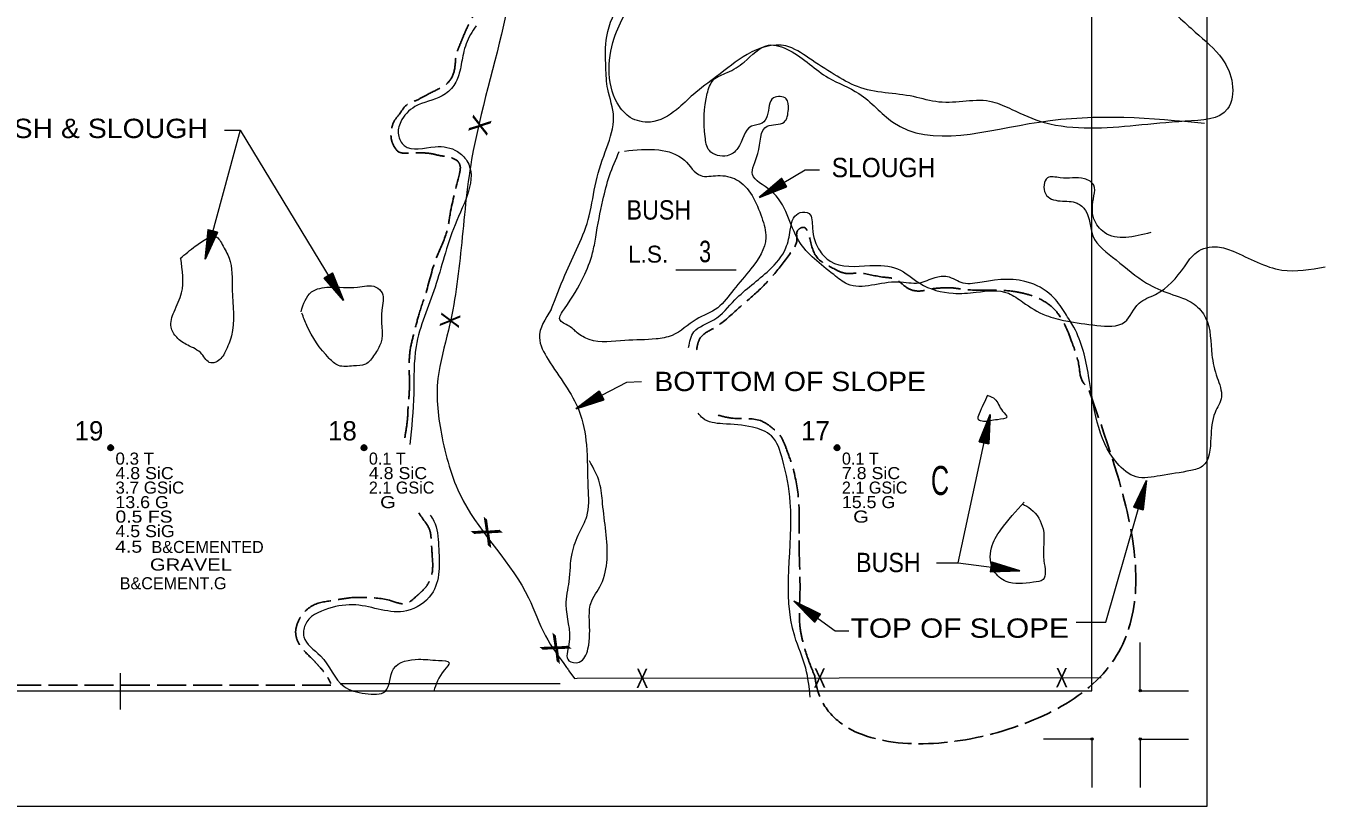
# Model space of a CAD drawing. Extents: x -577 to 499, y -450 to 700.
# Drawn here: x -39 to 499, y -450 to -127 of the extents above; entities that cross this region are included whole.
import ezdxf
from ezdxf.enums import TextEntityAlignment as Align

# ---------------------------------------------------------------- set-up
doc = ezdxf.new("R2010")
doc.units = 0
doc.header["$LTSCALE"] = 2
doc.header["$PDMODE"] = 32
doc.header["$PDSIZE"] = 1
doc.linetypes.add('LONG_DASHED', pattern=[7.5, 6, -1.5])
for name, color, linetype, lineweight in [('1', 7, 'Continuous', 13), ('2', 7, 'Continuous', 35), ('3', 7, 'Continuous', 13), ('4', 7, 'Continuous', 25)]:
    doc.layers.add(name, color=color, linetype=linetype, lineweight=lineweight)

msp = doc.modelspace()

# ---------------------------------------------------------------- linework, layer by layer
at = {"layer": '1'}
for p, q in [((230.048, -228.15), (255.048, -228.15)), ((422.281, -402.333), (422.281, -382.333)), ((-0.017, -395.027), (-0.017, -410.027)), ((-402.391, -402.333), (402.281, -402.333)), ((422.281, -402.333), (442.281, -402.333)), ((402.281, -422.333), (382.281, -422.333)), ((402.281, -422.333), (402.281, -442.333)), ((422.281, -422.333), (422.281, -442.333)), ((422.281, -422.333), (442.281, -422.333)), ((-450.017, -450.027), (449.983, -450.027))]:
    msp.add_line(p, q, dxfattribs=at)
for points in [[(449.983, -450.027), (449.983, 399.973), (449.983, 699.973), (-450.017, 699.973), (-450.017, 49.973), (-450.017, -450.027)], [(402.281, -402.333), (402.281, 402.339), (-402.391, 402.339)]]:
    msp.add_lwpolyline(points, dxfattribs=at)
for p in [(422.281, -402.333), (402.281, -422.333), (422.281, -422.333)]:
    msp.add_point(p, dxfattribs=at)
at = {"layer": '2', "linetype": 'LONG_DASHED', "lineweight": 25}
msp.add_line((87.286, -400), (-302.391, -400), dxfattribs=at)
at = {"layer": '2'}
for centre in [(-3.938, -301.775), (100.962, -301.775), (296.775, -301.775)]:
    msp.add_circle(centre, 1, dxfattribs=at)
at = {"layer": '2', "linetype": 'LONG_DASHED', "lineweight": 25}
for points in [[(131.994, -74.666), (132.56, -78.069), (134.001, -82.389), (135.983, -85.629), (138.686, -87.969), (145.714, -96.068), (149.859, -100.748), (151.48, -107.767), (149.138, -116.767), (143.912, -127.386), (142.29, -130.986), (140.669, -134.946), (139.227, -138.906), (138.326, -145.745), (135.443, -150.965), (133.1, -152.585), (126.793, -155.825), (122.288, -158.165), (118.144, -160.324), (115.621, -163.744), (113.639, -166.264), (112.377, -169.864), (112.197, -173.644), (113.098, -176.524), (115.441, -179.403), (118.864, -179.943), (123.91, -179.763), (128.956, -180.123), (133.1, -181.023), (136.524, -181.563), (139.587, -183.003)], [(139.587, -183.003), (140.609, -184.619), (140.45, -188.43), (136.635, -204.944), (135.204, -212.406), (131.071, -222.727), (126.62, -237.494), (123.758, -246.386), (121.851, -253.531), (120.261, -260.2), (119.625, -267.345), (119.784, -274.649), (119.466, -282.112), (119.148, -285.764)], [(238.624, -261.328), (238.966, -259.398), (240.252, -256.186), (245.72, -252.331), (255.69, -244.3), (263.087, -237.875), (270.484, -230.165), (277.559, -221.17), (280.132, -215.709), (280.454, -211.854), (282.705, -210.569), (285.6, -215.709), (288.816, -223.419), (295.891, -227.916), (299.751, -229.523), (305.54, -229.523), (315.51, -231.129), (320.977, -232.093), (325.801, -235.626), (329.661, -236.911), (336.736, -235.947), (340.596, -235.626), (344.133, -235.626), (349.601, -236.269), (362.787, -236.59), (370.827, -237.232), (376.295, -238.517), (383.37, -241.73), (388.195, -246.227), (393.984, -258.113), (396.878, -267.75), (398.486, -274.496), (401.059, -278.03), (401.165, -278.247)], [(401.059, -278.03), (401.168, -400.823), (288.505, -401.296), (287.529, -396.247)], [(119.148, -285.764), (118.691, -292.346), (117.797, -298.15), (117.771, -298.415)], [(287.529, -396.247), (285.6, -391.428), (282.384, -381.149), (281.419, -375.687), (281.419, -361.553), (281.097, -344.206), (280.776, -322.683), (278.203, -309.19), (275.63, -301.802), (273.378, -296.983), (270.162, -293.771), (265.016, -290.558), (253.76, -289.595), (247.508, -288.277)], [(123.608, -328.731), (126.066, -332.302), (128.077, -335.651), (128.748, -339.669), (129.195, -346.588), (128.971, -354.401), (127.854, -357.303), (126.29, -359.758), (124.055, -361.99), (122.267, -363.553), (118.468, -366.232), (112.21, -365.116), (101.26, -363.776), (96.343, -363.776), (88.522, -364.892), (80.03, -366.901), (76.23, -369.803), (73.549, -374.044), (72.655, -378.285), (73.325, -381.411), (75.113, -384.536), (80.03, -389.67), (82.041, -391.902), (85.393, -395.92), (87.181, -399.268)]]:
    msp.add_spline(points, degree=3, dxfattribs=at)
at = {"layer": '2'}
for points in [[(-3.948, -300.888), (-3.218, -301.292), (-3.067, -302.14), (-3.752, -302.668), (-4.561, -302.438), (-4.847, -301.68), (-4.6, -301.118), (-4.027, -300.95), (-3.353, -301.444), (-3.37, -302.185), (-3.887, -302.444), (-4.409, -302.275), (-4.634, -301.629), (-4.05, -301.163), (-3.611, -301.697), (-3.651, -302.18), (-4.28, -302.045), (-4.134, -301.41), (-3.842, -301.961)], [(100.951, -300.888), (101.682, -301.292), (101.833, -302.14), (101.148, -302.668), (100.339, -302.438), (100.053, -301.68), (100.3, -301.118), (100.873, -300.95), (101.547, -301.444), (101.53, -302.185), (101.013, -302.444), (100.491, -302.275), (100.266, -301.629), (100.85, -301.163), (101.288, -301.697), (101.249, -302.18), (100.62, -302.045), (100.766, -301.41), (101.058, -301.961)], [(296.764, -300.888), (297.495, -301.292), (297.646, -302.14), (296.961, -302.668), (296.152, -302.438), (295.866, -301.68), (296.113, -301.118), (296.686, -300.95), (297.36, -301.444), (297.343, -302.185), (296.826, -302.444), (296.304, -302.275), (296.079, -301.629), (296.663, -301.163), (297.101, -301.697), (297.062, -302.18), (296.433, -302.045), (296.579, -301.41), (296.871, -301.961)]]:
    msp.add_spline(points, degree=3, dxfattribs=at)
at = {"layer": '3'}
for p, q in [((189.244, -397.172), (406.028, -396.88)), ((91.415, -399.313), (182.147, -399.313))]:
    msp.add_line(p, q, dxfattribs=at)
msp.add_lwpolyline([(185.769, -394.07), (188.121, -397.302), (189.244, -397.172)], dxfattribs=at)
for points in [[(248.573, 33.881), (218.878, -3.63), (196.171, -32.418), (168.223, -83.015), (159.489, -123.144), (145.515, -182.465), (141.148, -219.104), (135.908, -253.127), (131.541, -273.191), (133.288, -297.617), (142.021, -323.788), (169.096, -363.917), (176.083, -379.619), (184.817, -392.705), (185.769, -394.07)], [(234.45, -55.931), (268.542, -55.612), (301.36, -75.026), (333.859, -77.89), (353.932, -81.709), (374.005, -90.301), (393.44, -96.03), (404.91, -101.122), (419.885, -107.487), (431.356, -117.034), (445.056, -129.764), (456.208, -140.903), (460.35, -151.087), (458.438, -161.589), (440.914, -166.681), (401.406, -169.545), (382.607, -167.318), (369.225, -161.907), (361.26, -158.725), (338.957, -158.725), (328.442, -156.497), (305.183, -152.36), (295.625, -147.268), (285.11, -140.585), (275.552, -135.493), (259.621, -138.993), (246.876, -148.223), (237.318, -155.542), (230.308, -161.907), (219.475, -166.999), (211.191, -165.09), (206.731, -160.634), (204.5, -132.31), (214.377, -112.897), (220.431, -100.804), (224.892, -91.256), (228.078, -81.709), (230.308, -71.207), (232.857, -57.522)], [(178.419, -244.641), (184.088, -230.384), (194.184, -205.779), (197.01, -191.661), (201.453, -177.544), (204.279, -165.039), (201.856, -153.342), (201.049, -144.468), (201.453, -131.561), (207.51, -116.636), (217.202, -102.116), (225.278, -80.738), (227.297, -66.217), (230.932, -54.116)], [(147.328, -127.258), (145.017, -130.809), (142.082, -138.628), (140.614, -145.958), (138.168, -151.822), (133.276, -156.219), (122.023, -160.617), (116.153, -166.97), (115.174, -172.345), (117.62, -176.743), (130.34, -177.232), (139.635, -179.186), (143.549, -183.096), (138.657, -209.483), (130.34, -235.382), (122.513, -259.815), (121.534, -279.361), (119.972, -300.504)], [(426.64, -212.734), (407.45, -212.734), (403.089, -207.071), (403.089, -197.487), (403.089, -193.13), (399.164, -190.517), (389.132, -190.081), (383.899, -190.081), (383.026, -196.615), (389.132, -199.665), (396.111, -200.536), (399.6, -203.586), (402.653, -214.041), (412.248, -224.06), (424.896, -233.644), (434.491, -238), (444.522, -242.357), (449.319, -248.02), (451.936, -263.267), (454.117, -272.851), (455.861, -280.692), (453.244, -287.227), (451.5, -297.682), (448.011, -309.444), (443.213, -311.187), (430.565, -313.365), (420.534, -313.8), (412.684, -308.137), (400.908, -271.98), (394.802, -251.941), (391.313, -246.277), (386.516, -239.743), (376.921, -233.644), (356.858, -233.209), (349.008, -233.644), (342.466, -231.03), (337.232, -231.466), (330.69, -233.644), (321.967, -233.209), (301.033, -234.08), (295.363, -230.159), (280.971, -216.219), (269.195, -195.309), (261.781, -188.774), (263.961, -180.061), (267.886, -168.735), (274.865, -166.993), (276.609, -161.765), (275.737, -157.409), (270.503, -156.973), (267.886, -164.379), (265.706, -167.428), (261.344, -168.735), (255.675, -177.883), (251.313, -180.933), (243.899, -178.755), (242.154, -173.091), (243.027, -155.23), (245.643, -149.567), (251.313, -146.518), (258.291, -142.162), (268.323, -135.191), (277.045, -137.37), (293.182, -148.696), (305.83, -155.23), (319.787, -166.993), (380.41, -166.993), (448.883, -167.428)], [(208.743, -178.992), (222.957, -178.568), (233.564, -182.806), (240.353, -189.163), (247.354, -189.163), (255.203, -190.858), (265.598, -206.539), (267.295, -214.803), (261.143, -227.729), (253.93, -236.417), (247.354, -243.834), (238.444, -248.707), (228.473, -255.276), (221.896, -256.759), (208.955, -257.395), (194.105, -256.971), (189.226, -254.217), (185.831, -251.462), (182.013, -248.707), (183.922, -244.257), (191.771, -231.12), (195.59, -221.16), (196.863, -214.591), (199.833, -199.334), (202.591, -189.163), (206.622, -179.204)], [(235.32, -260.268), (237.523, -253.882), (245.772, -248.846), (254.48, -240.606), (268.687, -228.247), (275.562, -219.091), (277.395, -211.767), (278.77, -206.731), (281.52, -204.442), (285.186, -204.9), (286.561, -210.851), (289.769, -220.464), (293.894, -224.584), (310.393, -226.415), (321.85, -227.789), (331.017, -233.74), (344.766, -237.86), (354.39, -237.402), (367.681, -237.86), (373.639, -241.522), (383.263, -247.015), (391.512, -249.304), (404.345, -251.135), (415.802, -249.762), (421.76, -241.98), (428.635, -238.318), (440.551, -226.873), (445.592, -220.922), (454.3, -218.633), (460.716, -220.464), (480.881, -228.247), (498.755, -226.873)], [(24.892, -223.463), (31.094, -218.361), (36.202, -215.081), (39.121, -214.17), (42.222, -217.632), (45.141, -223.281), (46.418, -236.401), (46.054, -255.534), (43.499, -262.094), (40.216, -266.102), (37.479, -266.649), (33.831, -263.005), (27.993, -259.36), (23.432, -256.08), (21.061, -251.889), (22.338, -245.512), (25.439, -237.676), (25.074, -223.463)], [(74.877, -245.512), (79.256, -237.312), (86.553, -235.308), (98.228, -235.308), (105.89, -235.308), (108.445, -237.676), (108.262, -244.783), (107.897, -258.449), (105.343, -263.187), (101.512, -267.196), (96.587, -267.925), (90.384, -267.742), (86.553, -264.827), (77.249, -251.161), (75.242, -246.058)], [(178.419, -244.641), (173.552, -256.188), (177.203, -265.304), (189.98, -286.575), (193.022, -300.553), (193.63, -318.178), (193.022, -330.332), (189.98, -337.017), (186.938, -345.526), (185.721, -357.073), (184.504, -366.796), (185.721, -383.205), (185.721, -389.89), (189.98, -390.498), (193.63, -385.029), (194.239, -372.874), (194.847, -366.189), (199.106, -358.288), (201.54, -347.957), (199.715, -324.863), (198.498, -316.354), (194.239, -307.238)], [(359.23, -280.196), (362.081, -281.62), (365.287, -286.602), (367.069, -289.093), (363.149, -290.161), (357.449, -290.873), (355.311, -290.161), (355.667, -287.67), (357.449, -283.755), (359.23, -279.84)], [(285.645, -404.946), (283.811, -393.044), (279.228, -379.769), (277.395, -324.379), (274.187, -306.525), (269.604, -296.912), (261.813, -293.25), (249.439, -291.877), (241.189, -289.588), (239.245, -287.459)], [(373.482, -325.036), (377.045, -327.171), (382.033, -335.357), (382.389, -348.524), (382.033, -356.353), (378.113, -357.421), (366.712, -357.065), (361.724, -352.794), (360.655, -343.186), (364.575, -335.712), (374.194, -324.324)], [(128.352, -329.633), (129.851, -332.136), (131.808, -342.398), (128.873, -362.433), (118.599, -369.274), (97.562, -366.831), (86.31, -368.297), (76.526, -375.138), (76.036, -380.024), (82.886, -387.843), (92.67, -400.548), (101.476, -403.48), (109.793, -402.503), (113.217, -393.218), (123.491, -389.309), (131.808, -389.798), (136.211, -390.775), (134.254, -393.707), (129.851, -402.503)]]:
    msp.add_spline(points, degree=3, dxfattribs=at)
at = {"layer": '4', "lineweight": 13}
for p, q in [((49.679, -170.335), (35.181, -223.686)), ((346.907, -349.344), (372.432, -352.649))]:
    msp.add_line(p, q, dxfattribs=at)
for points in [[(43.193, -170.335), (49.679, -170.335), (92.409, -240.834)], [(289.545, -186.95), (283.557, -186.95), (264.472, -198.164)], [(215.794, -274.455), (209.616, -274.724), (188.664, -285.724)], [(337.927, -349.344), (346.907, -349.344), (360.142, -287.968)], [(395.813, -373.979), (408.019, -373.979), (424.874, -315.344)], [(301.637, -377.616), (296.046, -377.616), (278.872, -365.249)]]:
    msp.add_lwpolyline(points, dxfattribs=at)
at = {"layer": '4'}
for points in [[(264.472, -198.164), (275.832, -193.809), (273.806, -190.36)], [(35.181, -223.686), (40.258, -212.63), (36.398, -211.581)], [(92.409, -240.834), (87.9, -229.535), (84.479, -231.609)], [(188.664, -285.724), (200.218, -281.917), (198.359, -278.375)], [(360.142, -287.968), (355.658, -299.276), (359.568, -300.12)], [(424.874, -315.344), (419.637, -326.324), (423.481, -327.429)], [(372.432, -352.649), (360.788, -349.124), (360.274, -353.091)], [(278.872, -365.249), (287.441, -373.885), (289.778, -370.639)]]:
    msp.add_lwpolyline(points, close=True, dxfattribs=at)
for points in [[(275.687, -193.757), (264.968, -197.874), (273.748, -190.584), (275.561, -193.629), (265.603, -197.501), (273.667, -190.831), (275.338, -193.586), (266.274, -197.106), (273.61, -191.117), (275.117, -193.466), (267.047, -196.676), (273.503, -191.406), (274.818, -193.389), (267.973, -196.159), (273.466, -191.728), (274.501, -193.274), (268.97, -195.597), (273.389, -192.149), (274.158, -193.202), (270.086, -195.017), (273.223, -192.548), (273.747, -193.143), (271.361, -194.244), (273.073, -193.06)], [(40.118, -212.694), (35.332, -223.132), (36.514, -211.781), (39.939, -212.69), (35.525, -222.421), (36.628, -212.014), (39.749, -212.816), (35.729, -221.67), (36.787, -212.259), (39.507, -212.885), (35.982, -220.822), (36.912, -212.54), (39.239, -213.038), (36.282, -219.804), (37.112, -212.796), (38.933, -213.178), (36.602, -218.706), (37.351, -213.151), (38.637, -213.366), (36.994, -217.511), (37.511, -213.552), (38.301, -213.611), (37.365, -216.066), (37.762, -214.024)], [(87.849, -229.681), (92.112, -240.343), (84.704, -231.663), (87.723, -229.808), (91.731, -239.713), (84.951, -231.741), (87.683, -230.033), (91.327, -239.048), (85.238, -231.794), (87.566, -230.255), (90.887, -238.28), (85.528, -231.897), (87.493, -230.554), (90.357, -237.361), (85.851, -231.929), (87.383, -230.873), (89.781, -236.372), (86.273, -232), (87.315, -231.217), (89.186, -235.264), (86.674, -232.161), (87.262, -231.629), (88.395, -234), (87.189, -232.304)], [(200.076, -281.857), (189.172, -285.458), (198.291, -278.596), (199.957, -281.724), (189.824, -285.116), (198.198, -278.838), (199.735, -281.67), (190.513, -284.754), (198.127, -279.122), (199.52, -281.54), (191.306, -284.361), (198.006, -279.405), (199.226, -281.448), (192.257, -283.889), (197.955, -279.725), (198.915, -281.319), (193.279, -283.375), (197.858, -280.142), (198.575, -281.23), (194.421, -282.849), (197.673, -280.532), (198.168, -281.151), (195.732, -282.137), (197.498, -281.037)], [(355.794, -299.206), (360.02, -288.528), (359.442, -299.926), (355.973, -299.199), (359.865, -289.248), (359.315, -299.699), (356.156, -299.064), (359.701, -290.009), (359.143, -299.464), (356.394, -298.982), (359.494, -290.869), (359.003, -299.189), (356.653, -298.815), (359.248, -291.902), (358.791, -298.944), (356.952, -298.659), (358.986, -293.016), (358.533, -298.602), (357.238, -298.455), (358.658, -294.229), (358.352, -298.21), (357.56, -298.193), (358.364, -295.692), (358.076, -297.753)], [(419.778, -326.263), (424.715, -315.895), (423.368, -327.228), (419.957, -326.269), (424.511, -316.603), (423.257, -326.993), (420.149, -326.146), (424.296, -317.351), (423.102, -326.746), (420.392, -326.08), (424.032, -318.196), (422.981, -326.463), (420.661, -325.931), (423.716, -319.209), (422.785, -326.204), (420.97, -325.796), (423.38, -320.302), (422.551, -325.846), (421.269, -325.612), (422.971, -321.491), (422.397, -325.442), (421.607, -325.372), (422.579, -322.931), (422.153, -324.967)], [(360.87, -349.254), (371.863, -352.574), (360.457, -352.949), (360.891, -349.432), (371.132, -352.48), (360.672, -352.804), (361.042, -349.603), (370.36, -352.38), (360.892, -352.613), (361.143, -349.834), (369.486, -352.245), (361.154, -352.451), (361.331, -350.078), (368.437, -352.086), (361.381, -352.219), (361.511, -350.363), (367.305, -351.918), (361.7, -351.933), (361.738, -350.63), (366.068, -351.693), (362.075, -351.72), (362.026, -350.929), (364.586, -351.522), (362.508, -351.407)], [(287.431, -373.731), (279.337, -365.585), (289.55, -370.677), (287.497, -373.565), (279.935, -366.016), (289.292, -370.702), (287.446, -373.342), (280.566, -366.471), (289.007, -370.765), (287.466, -373.092), (281.272, -367.004), (288.7, -370.784), (287.417, -372.788), (282.119, -367.643), (288.39, -370.88), (287.393, -372.451), (283.035, -368.329), (287.974, -370.98), (287.321, -372.108), (284.017, -369.115), (287.542, -370.989), (287.209, -371.708), (285.239, -369.97), (287.013, -371.058)]]:
    msp.add_lwpolyline(points, dxfattribs=at)

# ---------------------------------------------------------------- texts
at = {"layer": '1'}
msp.add_text('L.S.', height=7, dxfattribs=at).set_placement((218.565, -225.168), align=Align.CENTER)
at = {"layer": '1', "width": 0.75}
msp.add_text('3', height=8.89, dxfattribs=at).set_placement((242.146, -225.012), align=Align.CENTER)
at = {"layer": '2'}
for s, p in [(' 19', (-6.938, -298.775)), (' 18', (97.962, -298.775)), (' 17', (293.775, -298.775))]:
    msp.add_text(s, height=8, dxfattribs=at).set_placement(p, align=Align.RIGHT)
for s, width, p in [('0.3 T      ', 1.05, (-1.938, -308.775)), ('4.8 SiC    ', 1.1, (-1.938, -314.775)), ('4.8 SiC    ', 1.1, (102.962, -314.775)), ('7.8 SiC    ', 1.1, (298.775, -314.775)), ('3.7 GSiC   ', 1.05, (-1.938, -320.775)), ('13.6 G     ', 1.1, (-1.938, -326.775)), ('  G        ', 1.25, (102.962, -326.775)), ('15.5 G     ', 1.1, (298.775, -326.775)), ('0.5 FS     ', 1.2, (-1.938, -332.775)), ('  G        ', 1.25, (298.775, -332.775)), ('4.5 SiG    ', 1.1, (-1.938, -338.775)), ('4.5        ', 1.2, (-2.047, -345.21)), ('GRAVEL     ', 1.25, (12.347, -352.606))]:
    msp.add_text(s, height=5, dxfattribs=dict(at, width=width)).set_placement(p)
for s, p in [('0.1 T      ', (102.962, -308.775)), ('0.1 T      ', (298.775, -308.775)), ('2.1 GSiC   ', (102.962, -320.775)), ('2.1 GSiC   ', (298.775, -320.775)), ('B&CEMENTED ', (12.978, -345.337)), ('B&CEMENT.G ', (-0.174, -360.353))]:
    msp.add_text(s, height=5, dxfattribs=at).set_placement(p)
at = {"layer": '2', "width": 0.65}
msp.add_text('C', height=12, dxfattribs=at).set_placement((339.395, -321.324), align=Align.CENTER)
at = {"layer": '3'}
for rotation, width, p in [(252.865, 1.05, (145.139, -167.226)), (262.936, 0.85, (132.617, -248.594)), (320.477, 1.65, (149.363, -339.779)), (320.477, 1.65, (177.814, -387.733))]:
    msp.add_text('X', height=8, rotation=rotation, dxfattribs=dict(at, width=width)).set_placement(p, align=Align.CENTER)
at = {"layer": '3', "width": 0.7}
for p in [(216.105, -401.165), (289.6, -400.997), (389.775, -400.867)]:
    msp.add_text('X', height=8, dxfattribs=at).set_placement(p, align=Align.CENTER)
at = {"layer": '4'}
for s, width, p in [('BUSH & SLOUGH', 1.1, (-12.064, -173.632)), ('SLOUGH', 0.95, (315.978, -189.825)), ('BUSH', 0.9, (223.003, -207.369)), ('BOTTOM OF SLOPE', 1.1, (277.367, -278.335)), ('BUSH', 0.9, (318.01, -353.256)), ('TOP OF SLOPE', 1.15, (347.569, -380.409))]:
    msp.add_text(s, height=8, dxfattribs=dict(at, width=width)).set_placement(p, align=Align.CENTER)

doc.saveas('drawing.dxf')
